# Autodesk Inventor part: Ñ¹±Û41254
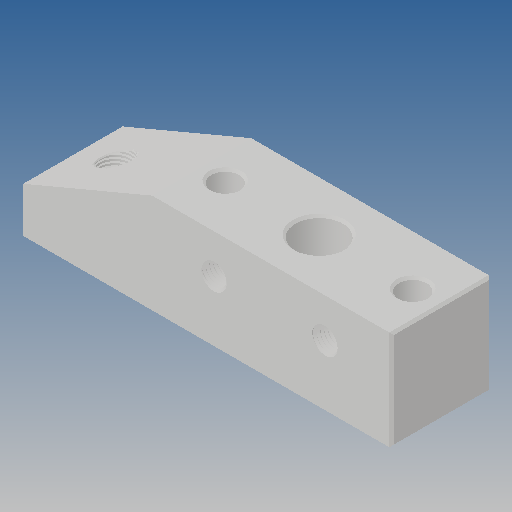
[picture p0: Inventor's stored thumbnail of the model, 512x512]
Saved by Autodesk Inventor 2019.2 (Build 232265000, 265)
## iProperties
Created: 2013-09
Part Number: Ñ¹±Û41254
Material: Ogólny
Document SubType Name: Modeling
Designer: CADENGINEERING4
Density: 1 g/cm^3
Appearance: Domyślna
Author: CADENGINEERING4
Revision Number: ÈÎºÎ
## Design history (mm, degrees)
feature "µ¹½Ç9"
node "Bryła1"
